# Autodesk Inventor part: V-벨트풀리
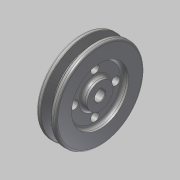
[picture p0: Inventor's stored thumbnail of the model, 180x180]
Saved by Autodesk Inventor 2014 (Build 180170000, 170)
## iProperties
Created: 2015-09
Part Number: V-벨트풀리
Material: 강철, 연강
Document SubType Name: Modeling
Designer: mduedu
Density: 1 g/cm^3
Appearance: Steel
Author: mduedu
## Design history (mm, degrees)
sketch "스케치1"
  geometry: L1 (-9.5, 0)-(9.5, 0); L2 (-9.5, 0)-(-9.5, 42.7); L3 (-9.5, 42.7)-(-4.877, 42.7); L4 (-4.877, 42.7)-(-1.953, 33.7); L5 (-1.953, 33.7)-(1.953, 33.7); L6 (1.953, 33.7)-(4.877, 42.7); L7 (4.877, 42.7)-(9.5, 42.7); L8 (9.5, 42.7)-(9.5, 0); L9 (0, 0)-(0, 33.7); L10 (-9.5, 40)-(9.5, 40); 3 further points
  constraints: 20 end point, 6 point on line, 3 perpendicular, 2 midpoint, 2 parallel, 2 symmetric about line, 1 coincident, 1 collinear, 1 equal length, 1 horizontal, 1 vertical, 1 vertical alignment
  dimensions: "d0" = 19 distance between parallel lines of L8 L2; "d5" = 6.3 distance between parallel lines of L5 L10; "d6" = 8 distance of point (4, 40) point (-4, 40); "d7" = 36 deg angle of L6 L4; "d40" = 2.7 distance between parallel lines of L10 L3; "d82" = 80 diameter of L10 L1; "d83" = 85.4 diameter of L3 L1 (derived)
revolve "회전1" sketch "스케치1" stored, may be unused: angle "d8" = 90 deg
sketch "스케치2"
  geometry: C1 r 12.5 at (0, 0); C2 r 27.5 at (0, 0); 1 further point
  constraints: 2 centre point, 2 coincident
  dimensions: "d9" = 25 diameter of C1; "d41" = 55 diameter of C2
extrude "돌출5" cut sketch "스케치2" distance "d42" = 5; taper "d43" = 0 deg
hole "구멍2" diameter "d46" = 10; stored, may be unused: countersink angle "d50" = 90 deg, drill point angle "d52" = 118 deg; dims "d47" = 6, "d48" = 4, "d49" = 2, "d51" = 8, "d84" = 10, "d85" = 10
sketch "스케치8"
  geometry: L1 (-1.5, 4.77)-(1.5, 4.77); L2 (1.5, 4.77)-(1.5, 6.4); L3 (1.5, 6.4)-(-1.5, 6.4); L4 (-1.5, 6.4)-(-1.5, 4.77); A1 r 5 centre (0, 0) between (-1.5, 4.77) and (1.5, 4.77) reference; 1 further point
  constraints: 8 end point, 2 parallel, 2 point on circle, 1 horizontal, 1 perpendicular
  dimensions: "d53" = 3 distance of L2.end L3.end; "d55" = 11.4 dimension on A1 L3
extrude "돌출6" cut sketch "스케치8" stored distance "d56" = 5; taper "d57" = 0 deg
fillet "모깎기5" dims "d71" = 2, "d72" = 1, "d73" = 0.5
fillet "모깎기7" dims "d75" = 3
fillet "모깎기8" dims "d76" = 3
sketch "스케치10"
  geometry: C1 r 35 at (0, 0); 1 further point
  constraints: 1 centre point, 1 coincident, 1 other
  dimensions: "d77" = 70 diameter of C1
extrude "돌출8" join sketch "스케치10" distance "d80" = 0.5; taper "d81" = 0 deg
chamfer "모따기4" distance "d88" = 0.5; stored, may be unused: second distance "d89" = 2, angle "d90" = 45 deg
sketch "스케치11" dims "d91" = 40
  geometry: C1 r 4 at (0, 20); 2 further points
  constraints: 2 vertical alignment, 1 centre point, 1 coincident, 2 other
  dimensions: "d92" = 8 diameter of C1
extrude "돌출9" cut sketch "스케치11" stored distance "d93" = 10; taper "d94" = 0 deg
node "솔리드1"
mirror "대칭2"
pattern_circular "원형 패턴2" dims angle "d96" = 360 deg
